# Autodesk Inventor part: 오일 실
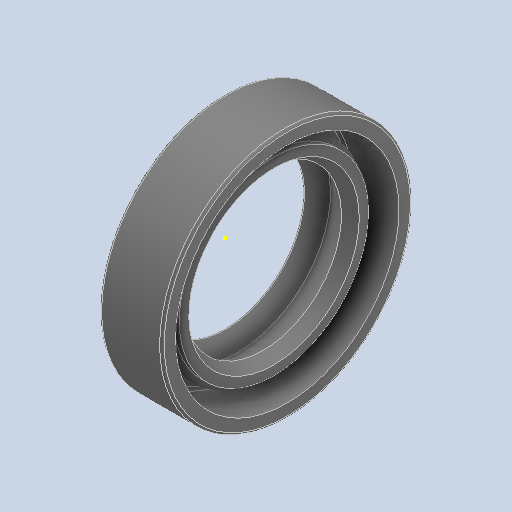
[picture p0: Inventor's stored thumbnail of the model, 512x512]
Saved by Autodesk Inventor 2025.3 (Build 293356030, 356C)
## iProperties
Created: 2025-08
Part Number: 오일 실
Material: 고무
Description: 오일-실
Document SubType Name: Modeling
Designer: user
Density: 0.93 g/cm^3
Appearance: 기본값
Author: jhkim
Sending System: Autodesk Inventor 2026
Preprocessor: ST-DEVELOPER v20.1
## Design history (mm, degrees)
sketch "스케치1"
  geometry: 1 further point
  constraints: 1 other
feature "Solid1"
node "솔리드1"
